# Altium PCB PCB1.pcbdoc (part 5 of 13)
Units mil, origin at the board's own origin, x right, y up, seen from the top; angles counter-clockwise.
Board outline 5895.51 x 5895.51 mil, 8 copper layers (Top Layer, L2_GND1, L3_SIG1, L4_GND2, L5_PWR, L6_SIG2, L7_GND3, Bottom Layer), stack 63.761 mil thick; 673 components, 558 nets, 2797 pads, 1861 vias.
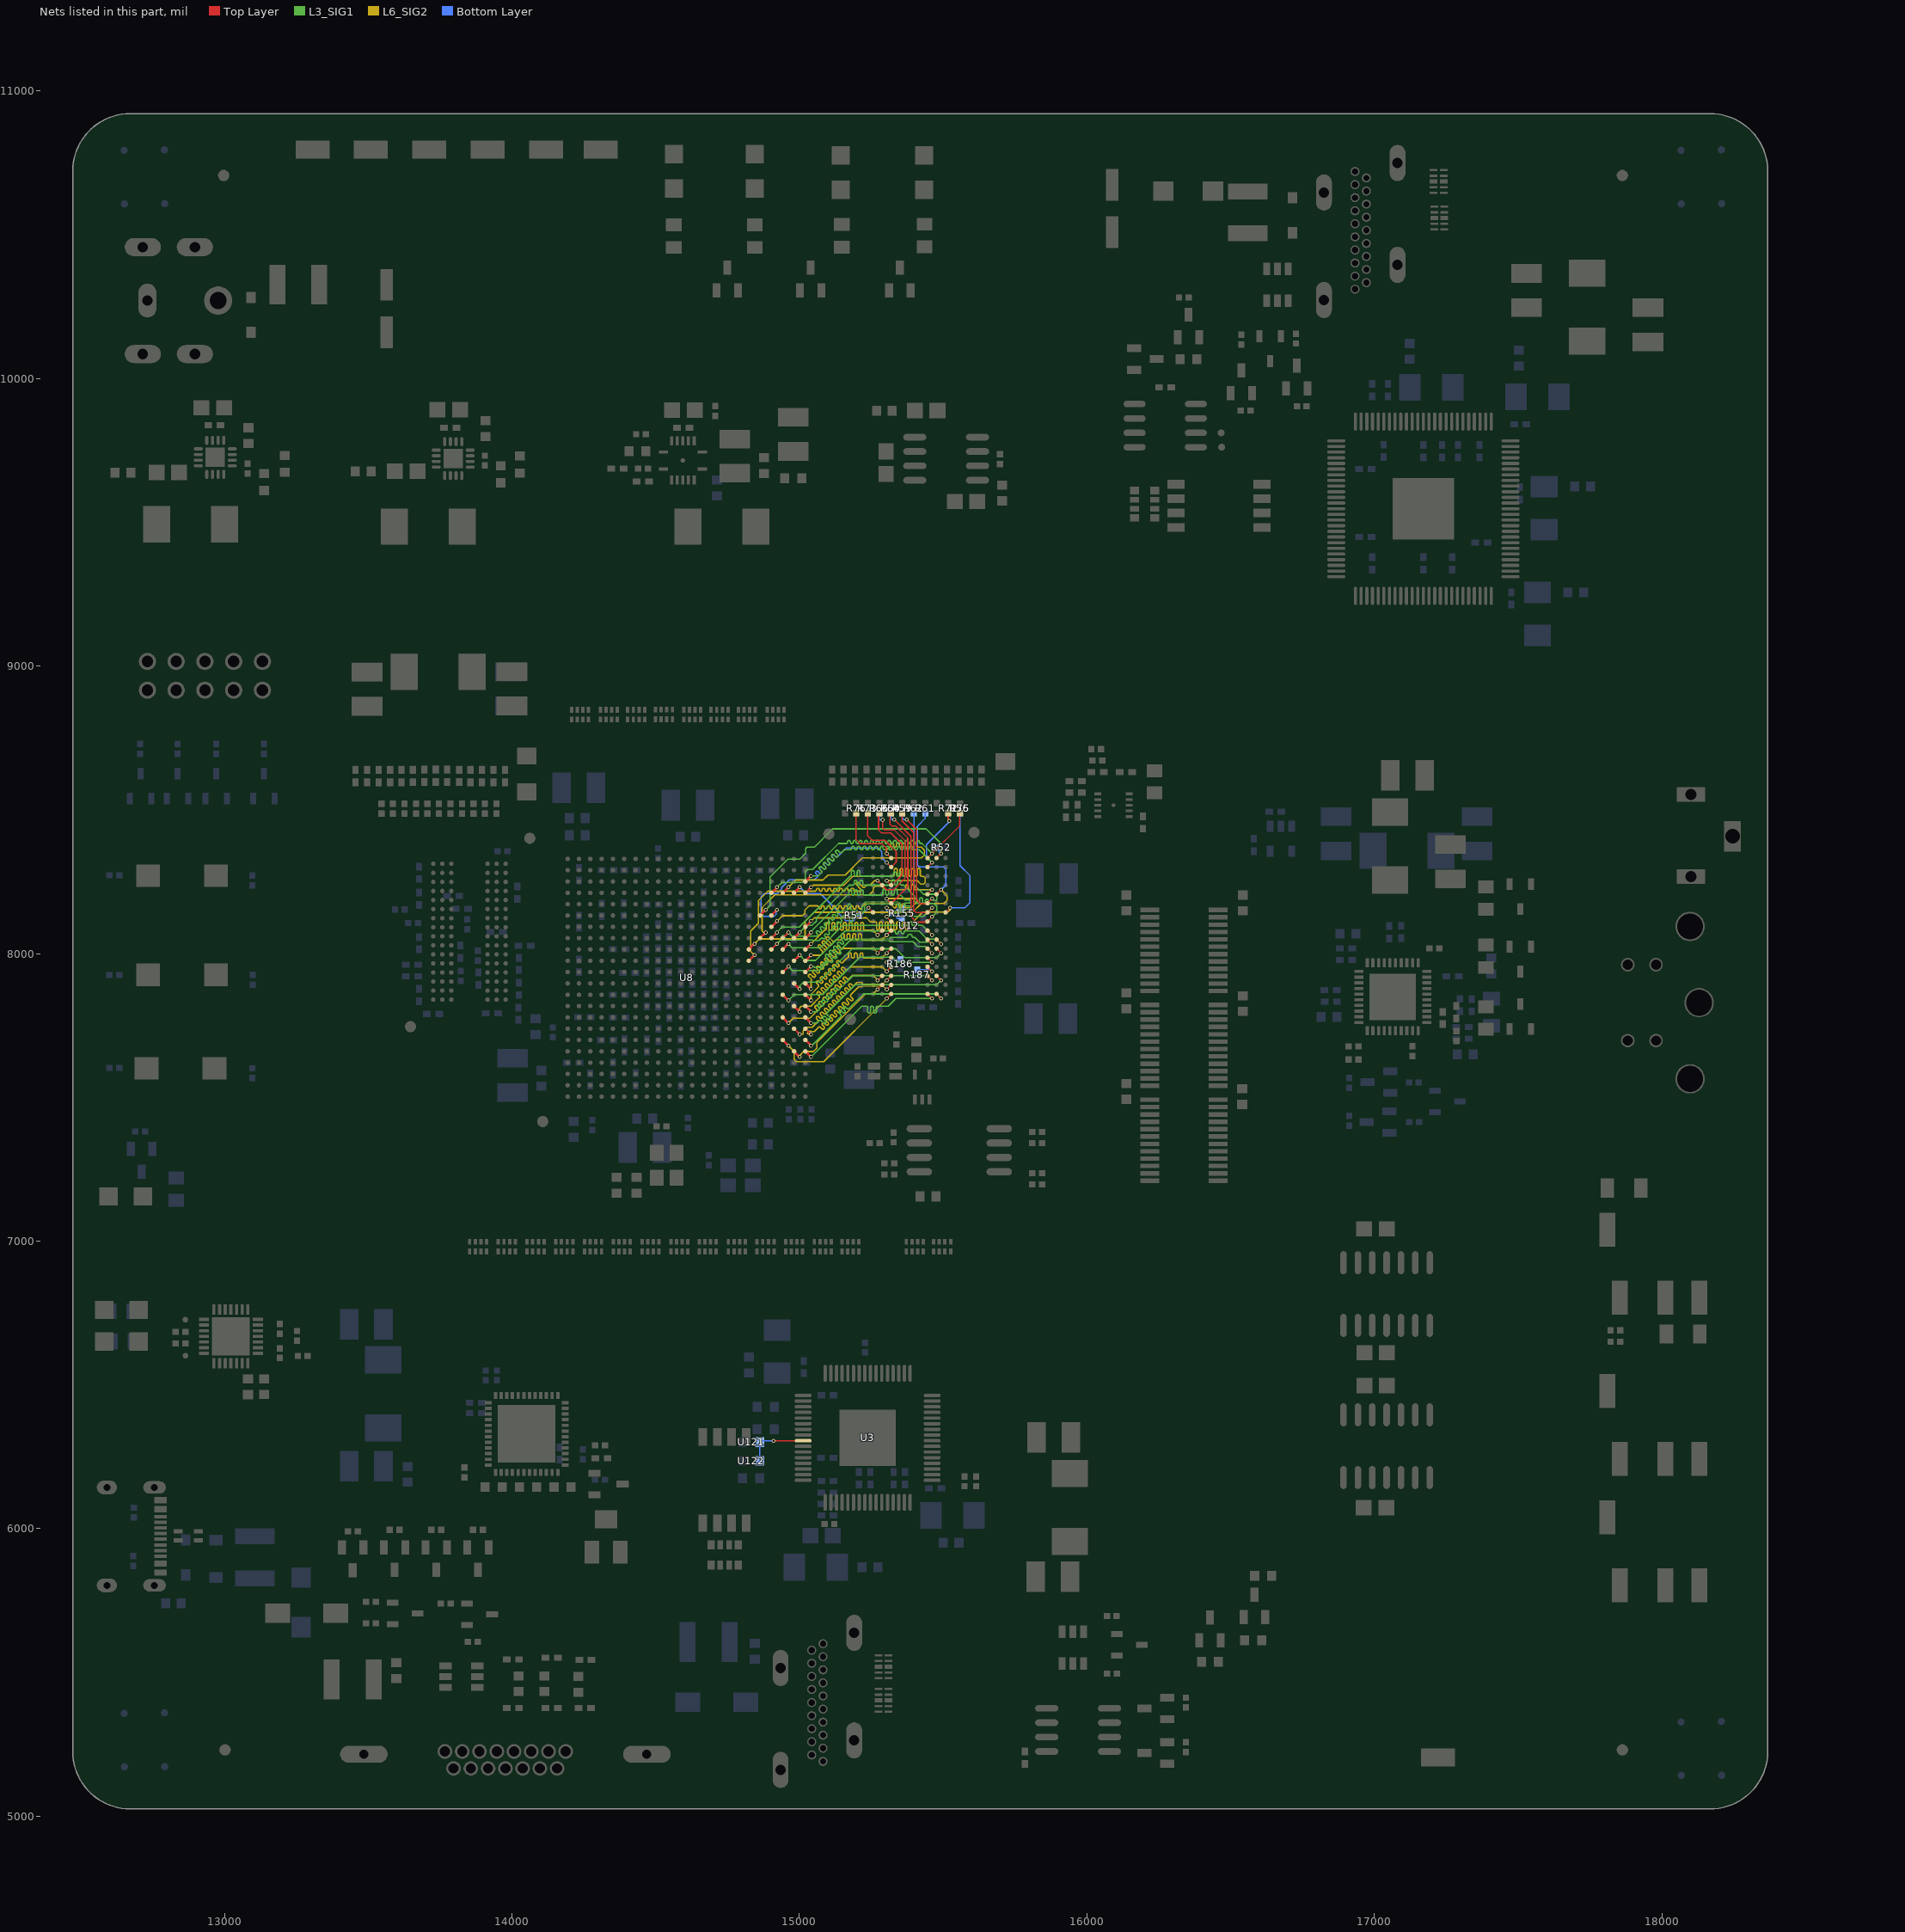
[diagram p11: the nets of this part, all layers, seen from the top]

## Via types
v1: diameter 23.62, hole 15.75, Top Layer to Bottom Layer, 621 vias
v2: diameter 13.8, hole 7.9, Top Layer to Bottom Layer, 567 vias
v3: diameter 13.78, hole 7.87, Top Layer to Bottom Layer, 529 vias
v4: diameter 13.78, hole 7.9, Top Layer to Bottom Layer, 114 vias
v5: diameter 15.75, hole 7.87, Top Layer to Bottom Layer, 16 vias
v6: diameter 24, hole 12, Top Layer to Bottom Layer, 10 vias
v7: diameter 11.81, hole 7.87, Top Layer to Bottom Layer, 4 vias

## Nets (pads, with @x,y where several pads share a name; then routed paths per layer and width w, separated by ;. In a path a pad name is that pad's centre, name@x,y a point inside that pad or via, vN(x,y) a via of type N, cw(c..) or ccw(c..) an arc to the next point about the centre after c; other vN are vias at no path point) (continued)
DW_A9: R72.1 U8.C22 U12.R3 | length 1059
  Top Layer w4.7: U12.R3@15445.35,8300.72 v2(15461.09,8316.47) ; R72.1@15517.53,8488.54 15517.53,8465.21 v3(15521.63,8461.11)
  Top Layer w7.9: U8.C22@15020.76,8250.65 v2(15040.44,8270.32)
  L3_SIG1 w5: v2(15040.44,8270.32) 15065.83,8270.32 15076.64,8281.14 ccw(c15073.11,8284.67) 15076.64,8288.21 15070.49,8294.35 cw(c15074.03,8297.89) 15077.56,8301.43 15083.71,8295.28 ccw(c15087.25,8298.81) 15090.78,8302.35 15084.64,8308.5 cw(c15088.17,8312.03) 15091.71,8315.57 15097.86,8309.42 ccw(c15101.39,8312.95) 15104.93,8316.49 15098.78,8322.64 cw(c15102.31,8326.17) 15105.85,8329.71 15112,8323.56 ccw(c15115.53,8327.1) 15119.07,8330.63 15112.92,8336.78 cw(c15116.46,8340.32) 15119.99,8343.85 15126.14,8337.7 ccw(c15129.67,8341.24) 15133.21,8344.77 15127.06,8350.92 cw(c15130.6,8354.46) 15134.13,8357.99 15140.28,8351.85 ccw(c15143.82,8355.38) 15147.35,8351.85 15156.32,8360.82 15176.46,8360.82 ccw(c15176.46,8365.82) 15181.46,8365.82 15181.46,8368.01 cw(c15186.46,8368.01) 15191.46,8368.01 15191.46,8365.82 ccw(c15196.46,8365.82) 15201.46,8365.82 15201.46,8368.01 cw(c15206.46,8368.01) 15211.46,8368.01 15211.46,8365.82 ccw(c15216.46,8365.82) 15221.46,8365.82 15221.46,8368.01 cw(c15226.46,8368.01) 15231.46,8368.01 15231.46,8365.82 ccw(c15236.46,8365.82) 15241.46,8365.82 15241.46,8368.01 cw(c15246.46,8368.01) 15251.46,8368.01 15251.46,8365.82 ccw(c15256.46,8365.82) 15261.46,8365.82 15261.46,8368.01 cw(c15266.46,8368.01) 15271.46,8368.01 15271.46,8365.82 ccw(c15276.46,8365.82) 15281.46,8365.82 15281.46,8368.01 cw(c15286.46,8368.01) 15291.46,8368.01 15291.46,8365.82 ccw(c15296.46,8365.82) 15301.46,8365.82 15301.46,8368.01 cw(c15306.46,8368.01) 15311.46,8368.01 15311.46,8365.82 ccw(c15316.46,8365.82) 15321.46,8365.82 15321.46,8368.01 cw(c15326.46,8368.01) 15331.46,8368.01 15331.46,8365.82 ccw(c15336.46,8365.82) 15341.46,8365.82 15341.46,8368.01 cw(c15346.46,8368.01) 15351.46,8368.01 15351.46,8365.82 ccw(c15356.46,8365.82) 15361.46,8365.82 15361.46,8368.01 cw(c15366.46,8368.01) 15371.46,8368.01 15371.46,8365.82 ccw(c15376.46,8365.82) 15381.46,8365.82 15381.46,8368.01 cw(c15386.46,8368.01) 15391.46,8368.01 15391.46,8365.82 ccw(c15396.46,8365.82) 15396.46,8360.82 15416.74,8360.82 v2(15461.09,8316.47)
  Bottom Layer w4.7: v2(15461.09,8316.47) 15442.03,8335.53 15442.03,8379.14 15521.63,8458.74 v3(15521.63,8461.11)
DW_A10: R60.1 U8.G19 U12.L7 | length 1216.3
  Top Layer w4.7: v2@15303.62,8190.48 U12.L7@15319.36,8174.75 ; R60.1@15315.59,8491.53 15315.59,8449.67 15322.24,8443.01 15336.04,8443.01 15376.99,8402.07 15376.99,8232.38 U12.L7@15319.36,8174.75 ; U12.L7@15318.48,8173.88 U12.L7@15319.36,8174.75
  Top Layer w7.9: U8.G19@14902.63,8093.16 v2(14922.31,8112.84)
  L6_SIG2 w5: v2(14922.31,8112.84) 14941.21,8131.75 15010.39,8131.75 15018.6,8139.96 15018.6,8151.13 15033.81,8166.34 15061.52,8166.34 cw(c15061.52,8161.34) 15066.52,8161.34 15066.52,8160.77 ccw(c15071.52,8160.77) 15076.52,8160.77 15076.52,8161.34 cw(c15081.52,8161.34) 15086.52,8161.34 15086.52,8160.77 ccw(c15091.52,8160.77) 15096.52,8160.77 15096.52,8161.34 cw(c15101.52,8161.34) 15106.52,8161.34 15106.52,8160.77 ccw(c15111.52,8160.77) 15116.52,8160.77 15116.52,8161.34 cw(c15121.52,8161.34) 15126.52,8161.34 15126.52,8160.77 ccw(c15131.52,8160.77) 15136.52,8160.77 15136.52,8161.34 cw(c15141.52,8161.34) 15146.52,8161.34 15146.52,8160.77 ccw(c15151.52,8160.77) 15156.52,8160.77 15156.52,8161.34 cw(c15161.52,8161.34) 15166.52,8161.34 15166.52,8160.77 ccw(c15171.52,8160.77) 15176.52,8160.77 15176.52,8161.34 cw(c15181.52,8161.34) 15186.52,8161.34 15186.52,8160.77 ccw(c15191.52,8160.77) 15196.52,8160.77 15196.52,8161.34 cw(c15201.52,8161.34) 15206.52,8161.34 15206.52,8160.77 ccw(c15211.52,8160.77) 15216.52,8160.77 15216.52,8161.34 cw(c15221.52,8161.34) 15221.52,8166.34 15222.24,8166.34 15228.56,8172.66 15317.82,8172.66 15331.9,8158.58 ccw(c15331.9,8163.58) 15336.9,8163.58 15336.9,8168.36 cw(c15341.9,8168.36) 15346.9,8168.36 15346.9,8163.58 ccw(c15351.9,8163.58) 15356.9,8163.58 15356.9,8168.36 cw(c15361.9,8168.36) 15366.9,8168.36 15366.9,8163.58 ccw(c15371.9,8163.58) 15371.9,8158.58 15387.72,8158.58 15409.34,8180.21 15409.34,8187.79 15405.55,8191.58 15304.72,8191.58 v2@15303.62,8190.48
  other v2: 15303.62,8190.6
DW_A11: R73.1 U8.F19 U12.R7 | length 1105.5
  Top Layer w4.7: R73.1@15237.04,8488.43 15237.04,8410.14 15252.8,8394.39 15297.08,8394.39 15336.57,8354.9 15336.57,8317.63 U12.R7@15319.31,8300.38 ; v2(15303.62,8316.47) U12.R7@15319.37,8300.72
  Top Layer w7.9: U8.F19@14902.63,8132.53 v2(14922.31,8152.21)
  Bottom Layer w4.7: v2(14922.31,8152.21) 14919.23,8149.13 14919.23,8135.92 14913.33,8130.02 14876.05,8130.02 14866.36,8139.71 14866.36,8197.43 14877.73,8208.8 14923.23,8208.8 14938.61,8224.18 14938.61,8229.87 14965.41,8256.67 15052.04,8256.67 15061.97,8266.61 ccw(c15058.44,8270.14) 15061.97,8273.68 15057.97,8277.68 cw(c15061.51,8281.22) 15065.04,8284.75 15069.05,8280.75 ccw(c15072.58,8284.29) 15076.12,8287.82 15072.11,8291.83 cw(c15075.65,8295.36) 15079.18,8298.9 15083.19,8294.89 ccw(c15086.72,8298.43) 15090.26,8301.96 15086.25,8305.97 cw(c15089.79,8309.5) 15093.33,8313.04 15097.33,8309.03 ccw(c15100.87,8312.57) 15104.4,8316.11 15100.4,8320.11 cw(c15103.93,8323.64) 15107.47,8327.18 15111.47,8323.18 ccw(c15115.01,8326.71) 15118.54,8330.25 15114.54,8334.25 cw(c15118.07,8337.79) 15121.61,8341.32 15125.61,8337.32 ccw(c15129.15,8340.85) 15132.68,8337.32 15162.94,8367.57 15273.84,8367.57 15286.64,8354.78 15286.64,8333.45 v2(15303.62,8316.47)
DW_A12: R65.1 U8.D22 U12.N7 | length 1171.5
  Top Layer w4.7: R65.1@15275.4,8490.97 15275.4,8429.55 15285.5,8419.45 15318.28,8419.45 15356.93,8380.8 15356.93,8272.8 U12.N7@15321.73,8237.61 ; v2(15303.62,8253.48) U12.N7@15319.37,8237.73
  Top Layer w7.9: U8.D22@15020.76,8211.27 v2(15040.44,8230.95)
  L6_SIG2 w5: v2(15040.44,8230.95) 15047.55,8238.06 15154.84,8238.06 15185.81,8269.03 15325.16,8269.03 ccw(c15325.16,8274.03) 15330.16,8274.03 15330.16,8291.17 cw(c15335.16,8291.17) 15340.16,8291.17 15340.16,8274.03 ccw(c15345.16,8274.03) 15350.16,8274.03 15350.16,8291.17 cw(c15355.16,8291.17) 15360.16,8291.17 15360.16,8274.03 ccw(c15365.16,8274.03) 15370.16,8274.03 15370.16,8291.17 cw(c15375.16,8291.17) 15380.16,8291.17 15380.16,8274.03 ccw(c15385.16,8274.03) 15390.16,8274.03 15390.16,8291.17 cw(c15395.16,8291.17) 15400.16,8291.17 15400.16,8274.03 ccw(c15405.16,8274.03) 15410.16,8274.03 15410.16,8291.17 cw(c15415.16,8291.17) 15420.16,8291.17 15420.16,8274.03 ccw(c15425.16,8274.03) 15425.16,8269.03 15431.92,8269.03 15437.48,8263.46 15437.48,8247.35 15432.11,8241.98 15422,8241.98 15410.5,8253.48 v2(15303.62,8253.48)
DW_A13: R75.1 U8.D19 U12.T3 | length 1020.4
  Top Layer w4.7: U12.T3@15445.35,8332.22 v2(15461.09,8347.97) 15557.62,8444.49 R75.1@15557.62,8488.08
  Top Layer w7.9: U8.D19@14902.63,8211.27 v2(14922.31,8230.95)
  L3_SIG1 w5: v2(14922.31,8230.95) 14939.34,8247.98 15009.12,8247.98 15020.49,8259.36 15020.49,8285.23 15027.49,8292.22 15045.62,8292.22 15136.3,8382.9 15162.24,8382.9 ccw(c15162.24,8387.9) 15167.24,8387.9 15167.24,8388.3 cw(c15172.24,8388.3) 15177.24,8388.3 15177.24,8387.9 ccw(c15182.24,8387.9) 15187.24,8387.9 15187.24,8388.3 cw(c15192.24,8388.3) 15197.24,8388.3 15197.24,8387.9 ccw(c15202.24,8387.9) 15207.24,8387.9 15207.24,8388.3 cw(c15212.24,8388.3) 15217.24,8388.3 15217.24,8387.9 ccw(c15222.24,8387.9) 15227.24,8387.9 15227.24,8388.3 cw(c15232.24,8388.3) 15237.24,8388.3 15237.24,8387.9 ccw(c15242.24,8387.9) 15247.24,8387.9 15247.24,8388.3 cw(c15252.24,8388.3) 15257.24,8388.3 15257.24,8387.9 ccw(c15262.24,8387.9) 15267.24,8387.9 15267.24,8388.3 cw(c15272.24,8388.3) 15277.24,8388.3 15277.24,8387.9 ccw(c15282.24,8387.9) 15287.24,8387.9 15287.24,8388.3 cw(c15292.24,8388.3) 15297.24,8388.3 15297.24,8387.9 ccw(c15302.24,8387.9) 15307.24,8387.9 15307.24,8388.3 cw(c15312.24,8388.3) 15317.24,8388.3 15317.24,8387.9 ccw(c15322.24,8387.9) 15327.24,8387.9 15327.24,8388.3 cw(c15332.24,8388.3) 15337.24,8388.3 15337.24,8387.9 ccw(c15342.24,8387.9) 15347.24,8387.9 15347.24,8388.3 cw(c15352.24,8388.3) 15357.24,8388.3 15357.24,8387.9 ccw(c15362.24,8387.9) 15367.24,8387.9 15367.24,8388.3 cw(c15372.24,8388.3) 15377.24,8388.3 15377.24,8387.9 ccw(c15382.24,8387.9) 15387.24,8387.9 15387.24,8388.3 cw(c15392.24,8388.3) 15397.24,8388.3 15397.24,8387.9 ccw(c15402.24,8387.9) 15407.24,8387.9 15407.24,8388.3 cw(c15412.24,8388.3) 15417.24,8388.3 15417.24,8387.9 ccw(c15422.24,8387.9) 15422.24,8382.9 15426.16,8382.9 v2(15461.09,8347.97)
DW_A14: R76.1 U8.D20 U12.T7 | length 1071.8
  Top Layer w4.7: R76.1@15197.38,8488.2 15197.38,8396.42 15211.88,8381.93 15287.1,8381.93 15301.24,8367.78 15301.24,8350.34 v2(15303.62,8347.97) U12.T7@15319.37,8332.22
  Top Layer w7.9: U8.D20@14942,8211.27 v2(14961.68,8230.95)
  L6_SIG2 w5: v2(14961.68,8230.95) 14986.66,8255.93 15081.92,8255.93 15099.4,8273.42 15159.56,8273.42 15218.54,8332.4 15424.02,8332.4 15434.12,8342.49 15434.12,8359.87 15424.01,8369.98 15412.48,8369.98 cw(c15412.48,8374.98) 15407.48,8374.98 15407.48,8379.83 ccw(c15402.48,8379.83) 15397.48,8379.83 15397.48,8374.98 cw(c15392.48,8374.98) 15387.48,8374.98 15387.48,8379.83 ccw(c15382.48,8379.83) 15377.48,8379.83 15377.48,8374.98 cw(c15372.48,8374.98) 15367.48,8374.98 15367.48,8379.83 ccw(c15362.48,8379.83) 15357.48,8379.83 15357.48,8374.98 cw(c15352.48,8374.98) 15347.48,8374.98 15347.48,8379.83 ccw(c15342.48,8379.83) 15337.48,8379.83 15337.48,8374.98 cw(c15332.48,8374.98) 15327.48,8374.98 15327.48,8379.83 ccw(c15322.48,8379.83) 15317.48,8379.83 15317.48,8374.98 cw(c15312.48,8374.98) 15312.48,8369.98 15303.31,8360.82 15303.31,8348.27 v2(15303.62,8347.97)
DW_BA0: R61.1 U8.J17 U12.M2 | length 1236.4
  Top Layer w4.7: U12.M2@15476.85,8206.24 v2(15492.59,8221.99)
  Top Layer w7.9: U8.J17@14823.89,8014.43 v2(14843.57,8034.1)
  L6_SIG2 w5: v2(14843.57,8034.1) 14860.64,8051.18 15011.93,8051.18 15019.83,8059.08 15019.83,8111.42 15052.3,8143.89 15393.54,8143.89 15424.44,8174.79 15503.26,8174.79 15514.01,8185.53 15514.01,8200.57 v2(15492.59,8221.99)
  Bottom Layer w4.7: R61.1@15437.17,8490.44 15437.17,8469.5 15409.8,8442.13 15409.8,8308.71 15416.93,8301.58 15501.12,8301.58 15509.17,8293.53 15509.17,8238.56 v2(15492.59,8221.99)
DW_BA1: R66.1 U8.K17 U12.N8 | length 1225.3
  Top Layer w4.7: v2(15272.12,8253.48) U12.N8@15287.87,8237.73 ; U12.N8@15287.8,8237.39 15303.12,8222.07 15328.03,8222.07 15366.79,8260.83 15366.79,8393.28 15329.52,8430.54 15295.9,8430.54 15289.69,8436.75 15289.69,8464.97 v3(15289.84,8465.13)
  Top Layer w7.9: U8.K17@14823.89,7975.06 v2(14843.57,7994.73)
  L6_SIG2 w5: v2(14843.57,7994.73) 14830.72,8007.58 14830.72,8079.03 14857.03,8105.35 14857.03,8183.84 14890.1,8216.9 15054.11,8216.9 ccw(c15054.11,8221.9) 15059.11,8221.9 cw(c15064.11,8221.9) 15069.11,8221.9 ccw(c15074.11,8221.9) 15079.11,8221.9 cw(c15084.11,8221.9) 15089.11,8221.9 ccw(c15094.11,8221.9) 15099.11,8221.9 cw(c15104.11,8221.9) 15109.11,8221.9 ccw(c15114.11,8221.9) 15119.11,8221.9 cw(c15124.11,8221.9) 15129.11,8221.9 ccw(c15134.11,8221.9) 15139.11,8221.9 cw(c15144.11,8221.9) 15149.11,8221.9 ccw(c15154.11,8221.9) 15159.11,8221.9 cw(c15164.11,8221.9) 15169.11,8221.9 ccw(c15174.11,8221.9) 15179.11,8221.9 cw(c15184.11,8221.9) 15189.11,8221.9 ccw(c15194.11,8221.9) 15194.11,8216.9 15213.58,8216.9 ccw(c15210.04,8220.44) 15213.58,8223.98 15198.31,8239.24 cw(c15201.85,8242.78) 15205.38,8246.31 15220.65,8231.05 ccw(c15224.18,8234.58) 15227.72,8231.05 15234.94,8238.27 15246.11,8238.27 15261.32,8253.48 v2(15272.12,8253.48)
  Bottom Layer w4.7: R66.1@15277.42,8488.9 15277.42,8468.81 15281.1,8465.13 v3(15289.84,8465.13)
DW_BA2: R62.1 U8.H18 U12.M3 | length 1156.2
  Top Layer w4.7: U12.M3@15445.35,8206.24 v2(15461.09,8221.99)
  Top Layer w7.9: U8.H18@14863.26,8053.8 v2(14882.94,8073.47)
  L6_SIG2 w5: v2(14882.94,8073.47) 14882.67,8073.21 14875.14,8073.21 14870.09,8078.26 14870.09,8160.15 14914.36,8204.42 15243.08,8204.42 15256.18,8217.53 15256.18,8226.93 15264.08,8234.83 15284.11,8234.83 15296.96,8221.99 15364.47,8221.99 ccw(c15364.47,8226.99) 15369.47,8226.99 15369.47,8234.71 cw(c15374.47,8234.71) 15379.47,8234.71 15379.47,8226.99 ccw(c15384.47,8226.99) 15389.47,8226.99 15389.47,8234.71 cw(c15394.47,8234.71) 15399.47,8234.71 15399.47,8226.99 ccw(c15404.47,8226.99) 15404.47,8221.99 v2(15461.09,8221.99)
  Bottom Layer w4.7: R62.1@15396.67,8491.1 15398.28,8489.49 15398.28,8238.98 15415.28,8221.99 v2(15461.09,8221.99)
DW_CAS: R57.1 U8.H22 U12.K3 | length 1262
  Top Layer w4.7: R57.1@15355.24,8490.77 15356.62,8489.39 15356.62,8461.56 15396.88,8421.3 15396.88,8151.94 15406.39,8142.43 U12.K3@15444.57,8142.43 ; U12.K3@15445.35,8143.24 v2(15461.09,8158.98)
  Top Layer w7.9: U8.H22@15020.76,8053.8 v2(15040.44,8073.47)
  L3_SIG1 w5: v2(15040.44,8073.47) 15040.44,8077.16 15166.81,8203.53 ccw(c15166.81,8208.53) 15171.81,8208.53 15171.81,8217.03 cw(c15176.81,8217.03) 15181.81,8217.03 15181.81,8208.53 ccw(c15186.81,8208.53) 15191.81,8208.53 15191.81,8217.03 cw(c15196.81,8217.03) 15201.81,8217.03 15201.81,8208.53 ccw(c15206.81,8208.53) 15211.81,8208.53 15211.81,8217.03 cw(c15216.81,8217.03) 15221.81,8217.03 15221.81,8208.53 ccw(c15226.81,8208.53) 15226.81,8203.53 15285.22,8203.53 ccw(c15285.22,8208.53) 15290.22,8208.53 15290.22,8219.4 cw(c15295.22,8219.4) 15300.22,8219.4 15300.22,8208.53 ccw(c15305.22,8208.53) 15310.22,8208.53 15310.22,8219.4 cw(c15315.22,8219.4) 15320.22,8219.4 15320.22,8208.53 ccw(c15325.22,8208.53) 15330.22,8208.53 15330.22,8219.4 cw(c15335.22,8219.4) 15340.22,8219.4 15340.22,8208.53 ccw(c15345.22,8208.53) 15345.22,8203.53 15352.33,8203.53 15364.97,8190.89 ccw(c15369.97,8190.89) 15369.97,8185.89 15382.11,8185.89 cw(c15382.11,8180.89) 15382.11,8175.89 15369.97,8175.89 ccw(c15369.97,8170.89) 15369.97,8165.89 15382.11,8165.89 cw(c15382.11,8160.89) 15382.11,8155.89 15369.97,8155.89 ccw(c15369.97,8150.89) 15364.97,8150.89 15364.97,8142.55 15378.24,8129.27 15431.38,8129.27 v2(15461.09,8158.98)
DW_CK+: R155.1 U8.H20 U12.J7 | length 795.5
  Top Layer w4.7: v2(15303.62,8127.49) U12.J7@15319.37,8111.75
  Top Layer w6.2: U8.H20@14942,8053.8 v2(14961.68,8073.47)
  L3_SIG1 w3.5: 15232.2,8178.4 15344.89,8178.4
  L3_SIG1 w4.2: v2(14961.68,8073.47) 14974.18,8060.97 15046.74,8060.97 15047.15,8061.39 15062.35,8061.39 ccw(c15058.82,8064.92) 15062.35,8068.46 15059.94,8070.87 cw(c15063.48,8074.4) 15067.01,8077.94 15069.42,8075.53 ccw(c15072.96,8079.06) 15076.49,8082.6 15074.08,8085.01 cw(c15077.62,8088.55) 15081.15,8092.08 15083.56,8089.67 ccw(c15087.1,8093.21) 15090.64,8096.74 15088.22,8099.15 cw(c15091.76,8102.69) 15095.3,8106.22 15097.71,8103.81 ccw(c15101.24,8107.35) 15104.78,8110.88 15102.37,8113.29 cw(c15105.9,8116.83) 15109.44,8120.37 15111.85,8117.95 ccw(c15115.38,8121.49) 15118.92,8125.03 15116.51,8127.44 cw(c15120.04,8130.97) 15123.58,8134.51 15125.99,8132.1 ccw(c15129.53,8135.63) 15133.06,8139.17 15130.65,8141.58 cw(c15134.19,8145.11) 15137.72,8148.65 15140.13,8146.24 ccw(c15143.67,8149.77) 15147.2,8146.24 15150.89,8149.93 15164.03,8149.93 ccw(c15164.03,8154.93) 15169.03,8154.93 15169.03,8167.55 cw(c15174.03,8167.55) 15179.03,8167.55 15179.03,8154.93 ccw(c15184.03,8154.93) 15184.03,8149.93 15199.85,8149.93 15203.38,8146.4 ; 15202.74,8145.3 15211.69,8145.3 15218.47,8152.08 15218.47,8166.97 15229.8,8178.3 15230.96,8178.3 ; v2(15303.62,8127.49) 15315.37,8139.24 15346.16,8139.24 15352.26,8145.34 15352.26,8171.46 15345.87,8177.85
  Bottom Layer w4: v2(15303.62,8127.49) 15303.62,8129.79 15305.81,8131.99 15332.96,8131.99 15342.4,8122.55 R155.1@15356.13,8122.55
DW_CK-: R155.2 U8.J19 U12.K7 | length 798.4
  Top Layer w4.7: v2(15303.62,8158.98) U12.K7@15319.37,8143.24
  Top Layer w6.2: U8.J19@14902.63,8014.43 v2(14922.31,8034.1)
  L3_SIG1 w3.5: 15226.5,8164.27 15227.59,8164.27 15234.74,8171.42 15341.35,8171.42
  L3_SIG1 w4.2: v2(14922.31,8034.1) 14934.81,8046.6 ccw(c14934.81,8051.6) 14939.81,8051.6 14939.81,8059.17 cw(c14944.81,8059.17) 14949.81,8059.17 14949.81,8051.6 ccw(c14954.81,8051.6) 14954.81,8046.6 15046.74,8046.6 15047.15,8046.19 15068.65,8046.19 15075.09,8052.63 cw(c15078.63,8049.09) 15082.16,8052.63 ccw(c15085.7,8056.17) 15089.23,8059.7 cw(c15092.77,8063.24) 15096.3,8066.77 ccw(c15099.84,8070.31) 15103.38,8073.84 cw(c15106.91,8077.38) 15110.45,8080.91 ccw(c15113.98,8084.45) 15117.52,8087.99 cw(c15121.05,8091.52) 15124.59,8095.06 ccw(c15128.12,8098.59) 15131.66,8102.13 cw(c15135.2,8105.66) 15138.73,8109.2 ccw(c15142.27,8112.73) 15145.8,8116.27 cw(c15149.34,8119.8) 15145.8,8123.34 15157.19,8134.73 15169.71,8134.73 cw(c15169.71,8129.73) 15174.71,8129.73 15174.71,8114.04 ccw(c15179.71,8114.04) 15184.71,8114.04 15184.71,8129.73 cw(c15189.71,8129.73) 15189.71,8134.73 15201.04,8134.73 15202.51,8136.2 15203.42,8136.2 ; 15202.74,8137.3 15215,8137.3 15226.47,8148.77 15226.47,8164.15 ; v2(15303.62,8158.98) 15315.37,8147.24 15342.85,8147.24 15344.26,8148.65 15344.26,8168.31 15341.59,8170.98
  Bottom Layer w4: v2(15303.62,8158.98) 15303.62,8149.38 15305.81,8147.19 15332.96,8147.19 15342.4,8156.63 R155.2@15356.13,8156.63
DW_CKE: R51.1 U8.D21 U12.K9 | length 359.3
  Top Layer w4.7: v2(15240.63,8158.98) U12.K9@15256.38,8143.24
  Top Layer w7.9: U8.D21@14981.36,8211.27 v2(15001.04,8230.95)
  Bottom Layer w4.7: v2(15001.04,8230.95) 15023.12,8208.86 15072.94,8208.86 15137.08,8144.73 15137.08,8139.19 15161.43,8114.84 15188.08,8114.84 15205.02,8131.77 15213.42,8131.77 v2(15240.63,8158.98)
DW_D0: U8.N20 U12.E3 | length 631.4
  Top Layer w4.7: U12.E3@15445.35,7985.76 v2(15461.09,7970.02)
  Top Layer w7.9: U8.N20@14942,7856.94 v2(14961.68,7837.27)
  L3_SIG1 w5: v2(14961.68,7837.27) 14979.13,7854.72 14979.13,7856.37 14980.08,7857.32 15079.92,7857.32 15117,7894.4 ccw(c15113.47,7897.93) 15117,7901.47 cw(c15120.54,7905) 15124.07,7908.54 ccw(c15127.61,7912.07) 15131.14,7908.54 15210.1,7987.49 15324.48,7987.49 15341.95,7970.02 v2(15461.09,7970.02)
DW_D1: U8.N22 U12.F7 | length 632.8
  Top Layer w4.7: v2(15303.62,8001.52) U12.F7@15319.37,8017.26
  Top Layer w7.9: U8.N22@15020.76,7856.94 v2(15040.44,7837.27)
  L6_SIG2 w5: v2(15040.44,7837.27) 15040.44,7858.05 15065.77,7883.38 15065.77,7884.41 ccw(c15062.24,7887.94) 15065.77,7891.48 15060.49,7896.77 cw(c15064.02,7900.3) 15067.56,7903.84 15072.84,7898.55 ccw(c15076.38,7902.08) 15079.91,7905.62 15074.63,7910.91 cw(c15078.16,7914.44) 15081.7,7917.98 15086.99,7912.69 ccw(c15090.52,7916.23) 15094.06,7919.76 15088.77,7925.05 cw(c15092.31,7928.58) 15095.84,7932.12 15101.13,7926.83 ccw(c15104.66,7930.37) 15108.2,7933.9 15102.91,7939.19 cw(c15106.45,7942.73) 15109.98,7946.26 15115.27,7940.98 ccw(c15118.81,7944.51) 15122.34,7948.05 15117.05,7953.33 cw(c15120.59,7956.87) 15124.13,7960.4 ; 15124.12,7960.4 15129.41,7955.12 ccw(c15132.95,7958.65) 15136.48,7962.19 15131.2,7967.48 cw(c15134.73,7971.01) 15138.27,7974.55 15143.55,7969.26 ccw(c15147.09,7972.8) 15150.63,7969.26 15165.88,7984.52 ccw(c15165.88,7989.52) 15170.88,7989.52 15170.88,7997.22 cw(c15175.88,7997.22) 15180.88,7997.22 15180.88,7989.52 ccw(c15185.88,7989.52) 15190.88,7989.52 15190.88,7997.22 cw(c15195.88,7997.22) 15200.88,7997.22 15200.88,7989.52 ccw(c15205.88,7989.52) 15210.88,7989.52 15210.88,7997.22 cw(c15215.88,7997.22) 15220.88,7997.22 15220.88,7989.52 ccw(c15225.88,7989.52) 15225.88,7984.52 15286.62,7984.52 v2(15303.62,8001.52)
DW_D2: U8.M21 U12.F2 | length 624.8
  Top Layer w4.7: U12.F2@15476.85,8017.26 v2(15492.59,8001.52)
  Top Layer w7.9: U8.M21@14981.36,7896.3 v2(15001.04,7876.62)
  L3_SIG1 w5: v2(15001.04,7876.62) 15001.94,7877.52 15001.94,7888.23 15014.58,7900.87 15067.35,7900.87 15183.3,8016.83 15336.39,8016.83 15366.73,7986.49 15477.56,7986.49 v2(15492.59,8001.52)
DW_D3: U8.M22 U12.F8 | length 627.6
  Top Layer w4.7: v2(15272.12,8001.52) U12.F8@15287.87,8017.26
  Top Layer w7.9: U8.M22@15020.76,7896.3 v2(15040.44,7876.62)
  L6_SIG2 w5: v2(15040.44,7876.62) 15040.44,7905.06 ccw(c15036.9,7908.59) 15040.44,7912.13 15032.87,7919.7 cw(c15036.4,7923.23) 15039.94,7926.77 15047.51,7919.2 ccw(c15051.04,7922.73) 15054.58,7926.27 15047.01,7933.84 cw(c15050.54,7937.38) 15054.08,7940.91 15061.65,7933.34 ccw(c15065.19,7936.88) 15068.72,7940.41 15061.15,7947.98 cw(c15064.69,7951.52) 15068.22,7955.05 15075.79,7947.48 ccw(c15079.33,7951.02) 15082.86,7954.55 15075.29,7962.13 cw(c15078.83,7965.66) 15082.36,7969.2 15089.93,7961.63 ccw(c15093.47,7965.16) 15097.01,7968.7 15089.43,7976.27 cw(c15092.97,7979.8) 15096.51,7983.34 15104.08,7975.77 ccw(c15107.61,7979.3) 15111.15,7982.84 15103.58,7990.41 cw(c15107.11,7993.95) 15110.65,7997.48 15118.22,7989.91 ccw(c15121.75,7993.45) 15125.29,7996.98 15117.72,8004.55 cw(c15121.25,8008.09) 15124.79,8011.62 15132.36,8004.05 ccw(c15135.9,8007.59) 15139.43,8011.12 15131.86,8018.69 cw(c15135.4,8022.23) 15138.93,8025.77 15146.5,8018.19 ccw(c15150.04,8021.73) 15153.57,8018.19 ; 15153.63,8018.25 15257.16,8018.25 15272.12,8003.28 v2(15272.12,8001.52)
DW_D4: U8.J20 U12.H3 | length 631.4
  Top Layer w4.7: U12.H3@15445.35,8080.25 v2(15461.09,8064.51)
  Top Layer w7.9: U8.J20@14942,8014.43 v2(14961.68,8034.1)
  L3_SIG1 w5: v2(14961.68,8034.1) 14961.68,8033.62 14974.56,8020.74 15073.61,8020.74 15150.86,8097.99 15376.66,8097.99 ccw(c15376.66,8102.99) 15381.66,8102.99 15381.66,8104.83 cw(c15386.66,8104.83) 15391.66,8104.83 15391.66,8102.99 ccw(c15396.66,8102.99) 15401.66,8102.99 15401.66,8104.83 cw(c15406.66,8104.83) 15411.66,8104.83 15411.66,8102.99 ccw(c15416.66,8102.99) 15416.66,8097.99 15427.6,8097.99 v2(15461.09,8064.51)
DW_D5: U8.J22 U12.H8 | length 625.5
  Top Layer w4.7: v2(15272.12,8064.51) U12.H8@15287.87,8080.25
  Top Layer w7.9: U8.J22@15020.76,8014.43 v2(15040.44,8034.1)
  L6_SIG2 w5: v2(15040.44,8034.1) 15040.64,8034.1 15087.98,8081.44 ccw(c15087.98,8086.44) 15092.98,8086.44 15092.98,8103.38 cw(c15097.98,8103.38) 15102.98,8103.38 15102.98,8086.44 ccw(c15107.98,8086.44) 15112.98,8086.44 15112.98,8103.38 cw(c15117.98,8103.38) 15122.98,8103.38 15122.98,8086.44 ccw(c15127.98,8086.44) 15132.98,8086.44 15132.98,8103.38 cw(c15137.98,8103.38) 15142.98,8103.38 15142.98,8086.44 ccw(c15147.98,8086.44) 15152.98,8086.44 15152.98,8103.38 cw(c15157.98,8103.38) 15162.98,8103.38 15162.98,8086.44 ccw(c15167.98,8086.44) 15172.98,8086.44 15172.98,8103.38 cw(c15177.98,8103.38) 15182.98,8103.38 15182.98,8086.44 ccw(c15187.98,8086.44) 15192.98,8086.44 15192.98,8103.38 cw(c15197.98,8103.38) 15202.98,8103.38 15202.98,8086.44 ccw(c15207.98,8086.44) 15212.98,8086.44 15212.98,8103.38 cw(c15217.98,8103.38) 15222.98,8103.38 15222.98,8086.44 ccw(c15227.98,8086.44) 15227.98,8081.44 15255.19,8081.44 v2(15272.12,8064.51)
DW_D6: U8.K21 U12.G2 | length 633.6
  Top Layer w4.7: U12.G2@15476.85,8048.76 v2(15492.59,8033.02)
  Top Layer w7.9: U8.K21@14981.36,7975.06 v2(15001.04,7994.73)
  L3_SIG1 w5: v2(15001.04,7994.73) 15019.27,7976.49 15056.81,7976.49 15159.4,8079.08 15328.9,8079.08 cw(c15328.9,8074.08) 15333.9,8074.08 ccw(c15338.9,8074.08) 15343.9,8074.08 cw(c15348.9,8074.08) 15353.9,8074.08 ccw(c15358.9,8074.08) 15363.9,8074.08 cw(c15368.9,8074.08) 15368.9,8079.08 15415.64,8079.08 15444.39,8050.32 15475.28,8050.32 v2(15492.59,8033.02)
DW_D7: U8.K22 U12.H7 | length 630.6
  Top Layer w4.7: v2(15303.62,8064.51) U12.H7@15319.37,8080.25
  Top Layer w7.9: U8.K22@15020.76,7975.06 v2(15040.44,7994.73)
  L6_SIG2 w5: v2(15040.44,7994.73) 15040.93,7994.23 15073.27,7994.23 15079.93,8000.9 ccw(c15076.4,8004.43) 15079.93,8007.97 15066.41,8021.49 cw(c15069.95,8025.03) 15073.48,8028.56 15087,8015.04 ccw(c15090.54,8018.57) 15094.08,8022.11 15080.55,8035.63 cw(c15084.09,8039.17) 15087.62,8042.7 15101.15,8029.18 ccw(c15104.68,8032.72) 15108.22,8036.25 15094.69,8049.78 cw(c15098.23,8053.31) 15101.77,8056.85 15115.29,8043.32 ccw(c15118.82,8046.86) 15122.36,8043.32 15126.67,8047.63 15140.86,8047.63 ccw(c15140.86,8052.63) 15145.86,8052.63 15145.86,8064.2 cw(c15150.86,8064.2) 15155.86,8064.2 15155.86,8052.63 ccw(c15160.86,8052.63) 15165.86,8052.63 15165.86,8064.2 cw(c15170.86,8064.2) 15175.86,8064.2 15175.86,8052.63 ccw(c15180.86,8052.63) 15185.86,8052.63 15185.86,8064.2 cw(c15190.86,8064.2) 15195.86,8064.2 15195.86,8052.63 ccw(c15200.86,8052.63) 15205.86,8052.63 15205.86,8064.2 cw(c15210.86,8064.2) 15215.86,8064.2 15215.86,8052.63 ccw(c15220.86,8052.63) 15220.86,8047.63 15288.13,8047.63 15288.13,8049.01 v2(15303.62,8064.51)
DW_D8: U8.P21 U12.D7 | length 625.6
  Top Layer w4.7: v2(15303.62,7938.52) U12.D7@15319.37,7954.27
  Top Layer w7.9: U8.P21@14981.36,7817.57 v2(15001.04,7797.9)
  L6_SIG2 w5: v2(15001.04,7797.9) 15000.87,7798.07 15000.87,7811.3 15006.98,7817.41 15039.94,7817.41 15068.64,7846.1 ccw(c15065.1,7849.64) 15068.64,7853.17 15062.88,7858.93 cw(c15066.42,7862.46) 15069.95,7866 15075.71,7860.25 ccw(c15079.24,7863.78) 15082.78,7867.32 15077.02,7873.07 cw(c15080.56,7876.61) 15084.09,7880.14 15089.85,7874.39 ccw(c15093.38,7877.92) 15096.92,7881.46 15091.17,7887.21 cw(c15094.7,7890.75) 15098.24,7894.28 15103.99,7888.53 ccw(c15107.53,7892.07) 15111.06,7895.6 15105.31,7901.35 cw(c15108.84,7904.89) 15112.38,7908.43 15118.13,7902.67 ccw(c15121.67,7906.21) 15125.2,7909.74 15119.45,7915.5 cw(c15122.99,7919.03) 15126.52,7922.57 15132.27,7916.81 ccw(c15135.81,7920.35) 15139.35,7923.89 15133.59,7929.64 cw(c15137.13,7933.17) 15140.66,7936.71 15146.42,7930.96 ccw(c15149.95,7934.49) 15153.49,7938.03 15147.73,7943.78 cw(c15151.27,7947.32) 15154.81,7950.85 15160.56,7945.1 ccw(c15164.09,7948.63) 15167.63,7945.1 15176.49,7953.96 15288.19,7953.96 v2(15303.62,7938.52)
DW_D9: U8.P22 U12.C3 | length 632.4
  Top Layer w4.7: U12.C3@15445.35,7922.77 v2(15461.09,7907.02)
  Top Layer w7.9: U8.P22@15020.76,7817.57 v2(15040.44,7797.9)
  L3_SIG1 w5: v2(15040.44,7797.9) 15061.03,7797.9 15068.39,7805.25 ccw(c15064.85,7808.79) 15068.39,7812.32 15065.14,7815.57 cw(c15068.67,7819.11) 15072.21,7822.64 15075.46,7819.39 ccw(c15078.99,7822.93) 15082.53,7826.46 15079.28,7829.71 cw(c15082.82,7833.25) 15086.35,7836.78 15089.6,7833.54 ccw(c15093.14,7837.07) 15096.67,7840.61 15093.42,7843.86 cw(c15096.96,7847.39) 15100.49,7850.93 15103.74,7847.68 ccw(c15107.28,7851.21) 15110.81,7854.75 15107.56,7858 cw(c15111.1,7861.53) 15114.64,7865.07 15117.88,7861.82 ccw(c15121.42,7865.36) 15124.96,7868.89 15121.71,7872.14 cw(c15125.24,7875.68) 15128.78,7879.21 15132.03,7875.96 ccw(c15135.56,7879.5) 15139.1,7875.96 15186.37,7923.24 15444.88,7923.24 v2(15461.09,7907.02)
DW_D10: U8.R20 U12.C8 | length 625.6
  Top Layer w4.7: v2(15272.12,7907.02) U12.C8@15287.87,7922.77
  Top Layer w7.9: U8.R20@14942,7778.2 v2(14961.68,7758.52)
  L6_SIG2 w5: v2(14961.68,7758.52) 14978.38,7775.22 15036,7775.22 15059.37,7798.59 15059.37,7799.86 ccw(c15055.84,7803.4) 15059.37,7806.93 15055.09,7811.22 cw(c15058.62,7814.75) 15062.16,7818.29 15066.44,7814.01 ccw(c15069.98,7817.54) 15073.51,7821.08 15069.23,7825.36 cw(c15072.77,7828.9) 15076.3,7832.43 15080.58,7828.15 ccw(c15084.12,7831.68) 15087.66,7835.22 15083.37,7839.5 cw(c15086.91,7843.04) 15090.44,7846.57 15094.73,7842.29 ccw(c15098.26,7845.83) 15101.8,7849.36 15097.51,7853.64 cw(c15101.05,7857.18) 15104.59,7860.72 15108.87,7856.43 ccw(c15112.4,7859.97) 15115.94,7863.5 15111.66,7867.79 cw(c15115.19,7871.32) 15118.73,7874.86 15123.01,7870.57 ccw(c15126.55,7874.11) 15130.08,7877.65 15125.8,7881.93 cw(c15129.33,7885.46) 15132.87,7889 15137.15,7884.72 ccw(c15140.69,7888.25) 15144.22,7891.79 15139.94,7896.07 cw(c15143.48,7899.61) 15147.01,7903.14 15151.3,7898.86 ccw(c15154.83,7902.39) 15158.37,7905.93 15154.08,7910.21 cw(c15157.62,7913.75) 15161.15,7917.28 15165.44,7913 ccw(c15168.97,7916.54) 15172.51,7913 15183.37,7923.87 15256.32,7923.87 15272.12,7908.06 v2(15272.12,7907.02)
DW_D11: U8.R22 U12.C2 | length 633.4
  Top Layer w4.7: U12.C2@15476.85,7922.77 v2(15492.59,7907.02)
  Top Layer w7.9: U8.R22@15020.76,7778.2 v2(15040.44,7758.52)
  L3_SIG1 w5: v2(15040.44,7758.52) 15040.76,7758.85 15061.27,7758.85 15068.59,7766.16 cw(c15072.12,7762.63) 15075.66,7766.16 15083.94,7757.88 ccw(c15087.47,7761.42) 15091.01,7764.95 15082.73,7773.23 cw(c15086.26,7776.77) 15089.8,7780.31 15098.08,7772.03 ccw(c15101.61,7775.56) 15105.15,7779.1 15096.87,7787.38 cw(c15100.41,7790.91) 15096.87,7794.45 15194.13,7891.71 15477.28,7891.71 v2(15492.59,7907.02)
DW_D12: U8.U20 U12.A7 | length 522.1
  Top Layer w4.7: v2(15303.62,7844.03) U12.A7@15319.37,7859.78
  Top Layer w7.9: U8.U20@14942,7699.47 v2(14961.68,7679.79)
  L6_SIG2 w5: v2(14961.68,7679.79) 14981.28,7660.19 14981.28,7633.08 14989.67,7624.68 15085.08,7624.68 15303.62,7843.23 v2(15303.62,7844.03)
DW_D13: U8.U22 U12.A2 | length 635.5
  Top Layer w4.7: U12.A2@15476.85,7859.78 v2(15492.59,7844.03)
  Top Layer w7.9: U8.U22@15020.76,7699.47 v2(15040.44,7679.79)
  L3_SIG1 w5: v2(15040.44,7679.79) 15042.68,7679.79 15143.96,7781.07 ccw(c15140.43,7784.61) 15143.96,7788.14 15138.76,7793.35 cw(c15142.29,7796.88) 15145.83,7800.42 15151.03,7795.21 ccw(c15154.57,7798.75) 15158.11,7802.29 15152.9,7807.49 cw(c15156.44,7811.03) 15159.97,7814.56 15165.18,7809.36 ccw(c15168.71,7812.89) 15172.25,7809.36 15222.5,7859.61 15477.02,7859.61 v2(15492.59,7844.03)
DW_D14: U8.V21 U12.B8 | length 433
  Top Layer w4.7: v2(15272.12,7875.53) U12.B8@15287.87,7891.28
  Top Layer w7.9: U8.V21@14981.36,7660.1 v2(15001.04,7640.42)
  L6_SIG2 w5: v2(15001.04,7640.42) 15001.04,7645.36 15014.78,7659.1 15048.9,7659.1 15061.22,7671.43 15061.22,7691.17 15230.53,7860.48 15257.06,7860.48 v2(15272.12,7875.53)
DW_D15: U8.V22 U12.A3 | length 631.9
  Top Layer w4.7: U12.A3@15445.35,7859.78 v2(15461.09,7844.03)
  Top Layer w7.9: U8.V22@15020.76,7660.1 v2(15040.44,7640.42)
  L3_SIG1 w5: v2(15040.44,7640.42) 15216.83,7816.82 15232.69,7816.82 cw(c15232.69,7811.82) 15237.69,7811.82 15237.69,7798.33 ccw(c15242.69,7798.33) 15247.69,7798.33 15247.69,7811.82 cw(c15252.69,7811.82) 15257.69,7811.82 15257.69,7798.33 ccw(c15262.69,7798.33) 15267.69,7798.33 15267.69,7811.82 cw(c15272.69,7811.82) 15272.69,7816.82 15308.75,7816.82 15335.97,7844.03 v2(15461.09,7844.03)
DW_LDM: R186.1 U12.E7 | length 75
  Top Layer w4.7: v2(15303.62,7970.02) U12.E7@15319.37,7985.76
  Bottom Layer w4.7: v2(15303.62,7970.02) 15311.8,7978.19 R186.1@15353,7978.19
DW_LDQS+: U8.L20 U12.F3 | length 655.7
  Top Layer w4.7: U12.F3@15445.35,8017.26 v2(15461.09,8001.52)
  Top Layer w6.2: U8.L20@14942,7935.7 v2(14961.68,7955.37)
  L3_SIG1 w3.5: 15174.48,8045.35 15312.45,8045.35
  L3_SIG1 w4.2: v2(14961.68,7955.37) 14975.73,7941.32 15070.45,7941.32 15100.16,7971.03 cw(c15103.69,7967.49) 15107.23,7971.03 15107.85,7970.4 ccw(c15111.39,7973.94) 15114.93,7977.47 15114.3,7978.1 cw(c15117.84,7981.63) 15121.37,7985.17 15122,7984.54 ccw(c15125.53,7988.08) 15129.07,7991.62 15128.44,7992.24 cw(c15131.98,7995.78) 15135.51,7999.31 15136.14,7998.69 ccw(c15139.67,8002.22) 15143.21,8005.76 15142.58,8006.38 cw(c15146.12,8009.92) 15142.58,8013.45 15142.78,8013.45 15174.26,8044.93 ; 15312.45,8044.85 15316.27,8041.02 ; 15316.27,8041.36 15394.97,8041.36 15410.92,8025.41 15437.2,8025.41 v2(15461.09,8001.52)
DW_LDQS-: U8.L22 U12.G3 | length 655.7
  Top Layer w4.7: U12.G3@15445.35,8048.76 v2(15461.09,8033.02)
  Top Layer w6.2: U8.L22@15020.76,7935.7 v2(15040.44,7955.37)
  L3_SIG1 w3.5: 15171.47,8053.16 15172.25,8052.37 15311.96,8052.37 15312.74,8053.16
  L3_SIG1 w4.2: v2@15040.73,7955.18 15049.63,7955.18 15053.03,7951.78 15070.08,7951.78 15096.02,7977.72 ccw(c15092.49,7981.25) 15096.02,7984.79 15091.71,7989.1 cw(c15095.25,7992.64) 15098.78,7996.17 15103.1,7991.86 ccw(c15106.63,7995.39) 15110.17,7998.93 15105.85,8003.24 cw(c15109.39,8006.78) 15112.92,8010.32 15117.24,8006 ccw(c15120.77,8009.54) 15124.31,8013.07 15119.99,8017.39 cw(c15123.53,8020.92) 15127.07,8024.46 15131.38,8020.14 ccw(c15134.92,8023.68) 15138.45,8027.21 15134.14,8031.53 cw(c15137.67,8035.06) 15141.21,8038.6 15145.52,8034.29 ccw(c15149.06,8037.82) 15152.59,8041.36 15148.28,8045.67 cw(c15151.81,8049.21) 15155.35,8052.74 15159.66,8048.43 ccw(c15163.2,8051.96) 15166.73,8048.43 15171.47,8053.16 ; 15312.74,8053.16 15315.8,8056.22 ; 15315.51,8056.56 15371.49,8056.56 ccw(c15371.49,8061.71) 15376.64,8061.71 cw(c15381.79,8061.71) 15381.79,8066.86 15386.49,8066.86 cw(c15386.49,8061.71) 15391.64,8061.71 ccw(c15396.79,8061.71) 15396.79,8056.56 15401.27,8056.56 15418.3,8039.53 15454.57,8039.53 v2(15461.09,8033.02)
DW_ODT: R56.1 U8.G22 U12.K1 | length 1256
  Top Layer w4.7: U12.K1@15508.34,8143.24 v2(15524.08,8158.98)
  Top Layer w7.9: U8.G22@15020.76,8093.16 v2(15040.44,8112.84)
  L6_SIG2 w5: v2(15040.44,8112.84) 15051.71,8124.11 15233.3,8124.11 15246.88,8110.52 15263.3,8110.52 cw(c15263.3,8105.52) 15268.3,8105.52 15268.3,8087.45 ccw(c15273.3,8087.45) 15278.3,8087.45 15278.3,8105.52 cw(c15283.3,8105.52) 15288.3,8105.52 15288.3,8087.45 ccw(c15293.3,8087.45) 15298.3,8087.45 15298.3,8105.52 cw(c15303.3,8105.52) 15308.3,8105.52 15308.3,8087.45 ccw(c15313.3,8087.45) 15318.3,8087.45 15318.3,8105.52 cw(c15323.3,8105.52) 15328.3,8105.52 15328.3,8087.45 ccw(c15333.3,8087.45) 15338.3,8087.45 15338.3,8105.52 cw(c15343.3,8105.52) 15348.3,8105.52 15348.3,8087.45 ccw(c15353.3,8087.45) 15358.3,8087.45 15358.3,8105.52 cw(c15363.3,8105.52) 15368.3,8105.52 15368.3,8087.45 ccw(c15373.3,8087.45) 15378.3,8087.45 15378.3,8105.52 cw(c15383.3,8105.52) 15383.3,8110.52 15395.07,8110.52 15428.98,8144.44 15516.18,8144.44 15524.08,8152.34 v2(15524.08,8158.98)
  Bottom Layer w4.7: v2(15524.08,8158.98) 15575.41,8158.98 15593.53,8177.11 15593.53,8270.83 15558.33,8306.02 15558.33,8484.55 R56.1@15555.75,8487.13
DW_RAS: R54.1 U8.H21 U12.J3 | length 1302.6
  Top Layer w4.7: v3(15329.63,8466.29) 15388.01,8407.92 15388.01,8128.61 15407.27,8109.35 U12.J3@15444.22,8109.35 ; U12.J3@15445.35,8111.75 v2(15461.09,8127.49)
  Top Layer w7.9: U8.H21@14981.36,8053.8 v2(15001.04,8073.47)
  L3_SIG1 w5: v2(15001.04,8073.47) 15001.04,8074.14 15024.55,8097.66 15043.43,8097.66 15059.13,8113.36 15059.13,8124.2 15172.87,8237.95 ; 15172.87,8237.98 15185.53,8237.98 ccw(c15185.53,8242.98) 15190.53,8242.98 15190.53,8249.73 cw(c15195.53,8249.73) 15200.53,8249.73 15200.53,8242.98 ccw(c15205.53,8242.98) 15210.53,8242.98 15210.53,8249.73 cw(c15215.53,8249.73) 15220.53,8249.73 15220.53,8242.98 ccw(c15225.53,8242.98) 15225.53,8237.98 15316.02,8237.98 ccw(c15316.02,8242.98) 15321.02,8242.98 15321.02,8251.63 cw(c15326.02,8251.63) 15331.02,8251.63 15331.02,8242.98 ccw(c15336.02,8242.98) 15341.02,8242.98 15341.02,8251.63 cw(c15346.02,8251.63) 15351.02,8251.63 15351.02,8242.98 ccw(c15356.02,8242.98) 15356.02,8237.98 15361.84,8237.98 15400.3,8199.51 15400.3,8182.63 15408.2,8174.73 15413.31,8174.73 ccw(c15413.31,8179.73) 15418.31,8179.73 15418.31,8189.22 cw(c15423.31,8189.22) 15428.31,8189.22 15428.31,8179.73 ccw(c15433.31,8179.73) 15438.31,8179.73 15438.31,8184.22 cw(c15443.31,8184.22) 15448.31,8184.22 15448.31,8179.73 ccw(c15453.31,8179.73) 15453.31,8174.73 15467.02,8174.73 15477.5,8164.25 15477.5,8143.91 v2(15461.09,8127.49)
  Bottom Layer w4.7: R54.1@15317.37,8489.6 15317.37,8470.59 15321.66,8466.29 v3(15329.63,8466.29)
DW_RST: R52.1 U8.F18 U12.T2 | length 924.7
  Top Layer w4.7: U12.T2@15476.85,8332.22 v2(15492.59,8347.97)
  Top Layer w7.9: U8.F18@14863.26,8132.53 v2(14882.94,8152.21)
  L3_SIG1 w5: v2(14882.94,8152.21) 14897.63,8166.9 14897.63,8266.54 14959.93,8328.84 15001.6,8328.84 15021.96,8349.2 15021.96,8365.76 15026.79,8370.59 15052.67,8370.59 15115.64,8433.56 15440.85,8433.56 15492.59,8381.82 v2(15492.59,8347.97)
  Bottom Layer w4.7: R52.1@15474.99,8365.69 15474.99,8365.57 v2(15492.59,8347.97)
DW_UDM: R187.1 U12.D3 | length 75.9
  Top Layer w4.7: U12.D3@15445.35,7954.27 v2(15461.09,7938.52)
  Bottom Layer w4.7: R187.1@15409.64,7943.81 15455.81,7943.81 v2(15461.09,7938.52)
DW_UDQS+: U8.T21 U12.C7 | length 630.2
  Top Layer w4.7: v2(15303.62,7907.02) U12.C7@15319.37,7922.77
  Top Layer w6.2: U8.T21@14981.36,7738.84 v2(15001.04,7719.16)
  L6_SIG2 w3.5: 15218.67,7894.9 15291.39,7894.9 ; 15291.6,7895.12 15291.71,7895.12 v2(15303.62,7907.02)
  L6_SIG2 w4.2: v2(15001.04,7719.16) 15010.94,7719.16 15013.14,7721.35 15013.14,7730.75 15026.72,7744.33 15045.02,7744.33 15063.54,7762.85 ccw(c15060.01,7766.39) 15063.54,7769.92 15060.07,7773.39 cw(c15063.61,7776.93) 15067.14,7780.46 15070.61,7776.99 ccw(c15074.15,7780.53) 15077.68,7784.06 15074.22,7787.53 cw(c15077.75,7791.07) 15081.29,7794.6 15084.75,7791.14 ccw(c15088.29,7794.67) 15091.83,7798.21 ; 15091.83,7798.21 15088.36,7801.67 cw(c15091.89,7805.21) 15095.43,7808.75 15098.9,7805.28 ccw(c15102.43,7808.81) 15105.97,7812.35 15102.5,7815.82 cw(c15106.03,7819.35) 15109.57,7822.89 15113.04,7819.42 ccw(c15116.57,7822.96) 15120.11,7826.49 15116.64,7829.96 cw(c15120.18,7833.49) 15123.71,7837.03 15127.18,7833.56 ccw(c15130.72,7837.1) 15134.25,7840.63 15130.78,7844.1 cw(c15134.32,7847.64) 15137.85,7851.17 15141.32,7847.7 ccw(c15144.86,7851.24) 15148.39,7854.78 15144.93,7858.24 cw(c15148.46,7861.78) 15152,7865.31 15155.46,7861.85 ccw(c15159,7865.38) 15162.54,7868.92 15159.07,7872.39 cw(c15162.6,7875.92) 15166.14,7879.46 15169.61,7875.99 ccw(c15173.14,7879.52) 15176.68,7883.06 15173.21,7886.53 cw(c15176.75,7890.06) 15180.28,7893.6 15183.75,7890.13 ccw(c15187.28,7893.67) 15190.82,7890.13 15199.95,7899.26 15216.33,7899.26 15219.14,7896.45
DW_UDQS-: U8.T22 U12.B7 | length 631.5
  Top Layer w4.7: v2(15303.62,7875.53) U12.B7@15319.37,7891.28
  Top Layer w6.2: U8.T22@15020.76,7738.84 v2(15040.44,7719.16)
  L6_SIG2 w3.5: 15218.55,7887.89 15291.27,7887.89 v2(15303.62,7875.53)
  L6_SIG2 w4.2: v2(15040.44,7719.16) 15030.53,7719.16 15028.34,7721.35 15028.34,7724.45 15034.37,7730.49 15040.57,7730.49 15041.92,7729.13 15051.32,7729.13 15066.11,7743.93 cw(c15069.65,7740.39) 15073.18,7743.93 15078.67,7738.44 ccw(c15082.21,7741.97) 15085.74,7745.51 15080.26,7751 cw(c15083.79,7754.53) 15087.33,7758.07 15092.82,7752.58 ccw(c15096.35,7756.12) 15099.89,7759.65 15094.4,7765.14 cw(c15097.93,7768.68) 15101.47,7772.21 15106.96,7766.72 ccw(c15110.49,7770.26) 15114.03,7773.79 15108.54,7779.28 cw(c15112.08,7782.82) 15115.61,7786.35 15121.1,7780.86 ccw(c15124.64,7784.4) 15128.17,7787.94 15122.68,7793.43 cw(c15126.22,7796.96) 15129.75,7800.5 15135.24,7795.01 ccw(c15138.78,7798.54) 15142.31,7802.08 15136.82,7807.57 cw(c15140.36,7811.1) 15143.89,7814.64 15149.38,7809.15 ccw(c15152.92,7812.68) 15156.46,7816.22 15150.97,7821.71 cw(c15154.5,7825.24) 15158.04,7828.78 15163.53,7823.29 ccw(c15167.06,7826.83) 15170.6,7830.36 15165.11,7835.85 cw(c15168.64,7839.39) 15172.18,7842.92 15177.67,7837.43 ccw(c15181.2,7840.97) 15184.74,7844.5 15179.25,7849.99 cw(c15182.79,7853.53) 15179.25,7857.06 15206.24,7884.06 15216.33,7884.06 15218.7,7886.43 15218.7,7887.46
DW_WE: R59.1 U8.H19 U12.L3 | length 1229.2
  Top Layer w4.7: v3(15373.11,8466.39) 15407.69,8431.81 15407.69,8186.36 15421.26,8172.79 U12.L3@15444.96,8172.79 ; U12.L3@15445.35,8174.74 v2(15461.09,8190.48)
  Top Layer w7.9: U8.H19@14902.63,8053.8 v2(14922.31,8073.47)
  L3_SIG1 w5: v2(14922.31,8073.47) 14922.31,8074.88 14940.88,8093.46 14942.57,8091.77 14999.19,8091.77 15175.66,8268.24 15175.66,8269.26 ccw(c15175.66,8274.26) 15180.66,8274.26 15180.66,8284.09 cw(c15185.66,8284.09) 15190.66,8284.09 15190.66,8274.26 ccw(c15195.66,8274.26) 15200.66,8274.26 15200.66,8284.09 cw(c15205.66,8284.09) 15210.66,8284.09 15210.66,8274.26 ccw(c15215.66,8274.26) 15215.66,8269.26 15322.82,8269.26 ccw(c15322.82,8274.26) 15327.82,8274.26 15327.82,8278.88 cw(c15332.82,8278.88) 15337.82,8278.88 15337.82,8274.26 ccw(c15342.82,8274.26) 15347.82,8274.26 15347.82,8278.88 cw(c15352.82,8278.88) 15357.82,8278.88 15357.82,8274.26 ccw(c15362.82,8274.26) 15362.82,8269.26 15369.31,8269.26 15431.92,8206.64 15473.36,8206.64 15478.41,8201.59 15478.41,8186.25 15476.8,8184.63 15466.95,8184.63 v2(15461.09,8190.48)
  Bottom Layer w4.7: R59.1@15356.39,8487.55 15357.77,8486.17 15357.77,8470.68 15362.07,8466.39 v3(15373.11,8466.39)
EDGE: U3.9 U121.1 U122.2 | length 218.1
  Top Layer w4.7: v3(14909.36,6306.16) U3.9@15012.95,6306.16
  Bottom Layer w4.7: U122.2@14862.02,6236 U121.1@14862.02,6301 14867.18,6306.16 v3(14909.36,6306.16)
